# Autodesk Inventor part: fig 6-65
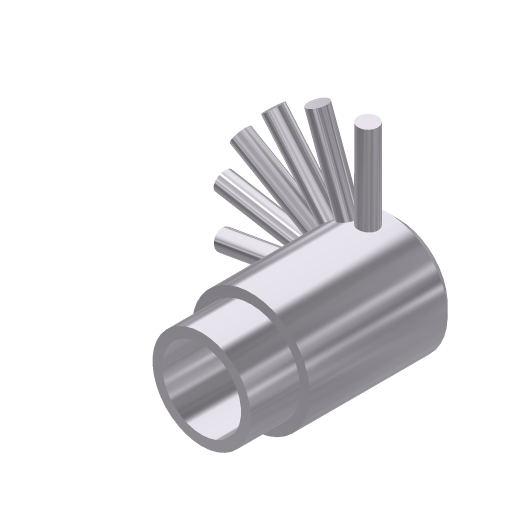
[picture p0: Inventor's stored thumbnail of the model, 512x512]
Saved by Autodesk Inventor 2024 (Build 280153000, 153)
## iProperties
Shininess: 77.0
Angle Display Precision: 2
Document Length Units: 11269
Document Angle Units: 11279
Document Time Units: 11290
Document Mass Units: 11283
Document Length Units Precision: 3
Document Angle Units Precision: 2
Compacted: True
Created: 2001-12
Part Number: fig 6-65
Document SubType Name: Modeling
Designer: Renu Muthoo
Density: 1 g/cm^3
Material: Generic
Appearance: Metal-AL-6061 (Polished)
Density: 0.0
Volumn: 0.0
Area: 0.0
PropertySet Name: Model Information
Control State: 0
Master: False
Checked Out: False
Author: Renu Muthoo
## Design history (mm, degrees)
sketch "Sketch2"
  geometry: L1 (-9.573, -4.327)-(-9.573, -5.327); L2 (-9.573, -5.327)-(-4.573, -5.327); L3 (-4.573, -5.327)-(-4.573, -6.327); L4 (-4.573, -6.327)-(9.427, -6.327); L5 (9.427, -6.327)-(10.427, -5.327); L6 (10.427, -5.327)-(10.427, -4.327); L7 (10.427, -4.327)-(-9.573, -4.327); L8 (-13.687, -0.327)-(14, -0.327)
  constraints: 16 end point, 5 parallel, 1 perpendicular, 1 vertical
  dimensions: "d9" = 20 distance of L6.end L1.start; "d10" = 5 distance of L1.end L2.end; "d11" = 12 diameter of L4 L8; "d12" = 10 diameter of L2 L8; "d13" = 8 diameter of L7 L8; "d14" = 45 deg angle of L5 L4; "d15" = 1 horizontal distance of L5.end L4.end
revolve "Revolution2" sketch "Sketch2" stored, may be unused: angle "d16" = 90 deg
workplane "Work Plane1"
workplane "Work Plane2"
sketch "Sketch3"
  geometry: L1 (-4, 8)-(4, 8) reference; C1 r 1 at (-0.098, 5)
  constraints: 1 centre point
  dimensions: "d18" = 3 distance from line of L1 C1.centre; "d19" = 2 diameter of C1
extrude "Extrusion1" join sketch "Sketch3" distance "d20" = 10; taper "d21" = 0 deg
pattern_circular "Circular Pattern3" dims angle "d29" = 20 deg
body "Solid1"
other parameters: "d17" = -1
